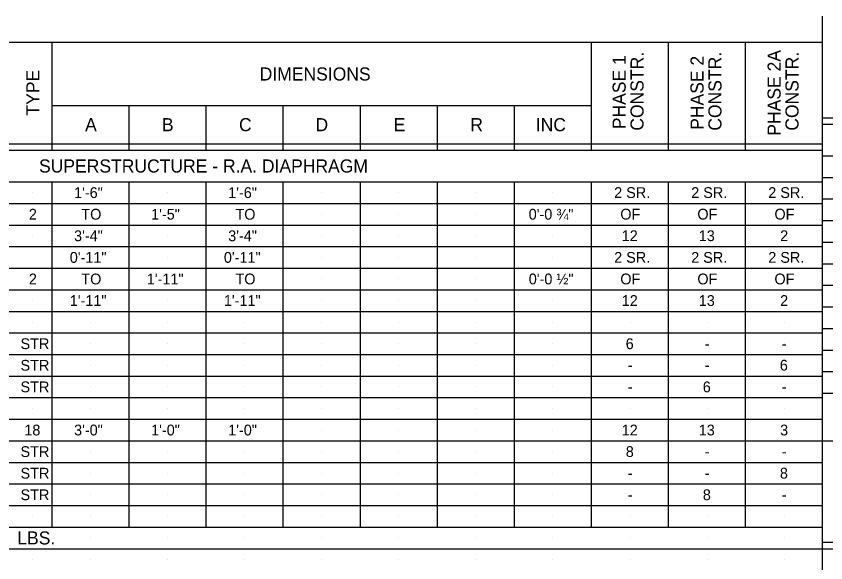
# Model space of a CAD drawing. Extents: x 0 to 34, y 0 to 22.
# Drawn here: x 6.29 to 16.8, y 7.18 to 14.27 of the extents above; entities that cross this region are included whole.
import ezdxf

# ---------------------------------------------------------------- set-up
doc = ezdxf.new("R2010")
doc.units = 0
doc.layers.add('BR_P_Gen_Text', color=7, linetype='Continuous')

msp = doc.modelspace()

# ---------------------------------------------------------------- linework, layer by layer
at = {"layer": 'BR_P_Gen_Text'}
for p, q in [((16.76, 7.701), (16.76, 14.272)), ((16.76, 3.872), (16.76, 14.272)), ((1.593, 13.935), (16.76, 13.935)), ((6.76, 12.535), (6.76, 13.935)), ((13.76, 12.535), (13.76, 13.935)), ((14.76, 12.535), (14.76, 13.935)), ((15.76, 12.535), (15.76, 13.935)), ((6.76, 13.112), (13.76, 13.112)), ((7.76, 12.535), (7.76, 13.112)), ((8.76, 12.535), (8.76, 13.112)), ((9.76, 12.535), (9.76, 13.112)), ((10.76, 12.535), (10.76, 13.112)), ((11.76, 12.535), (11.76, 13.112)), ((12.76, 12.535), (12.76, 13.112)), ((16.76, 12.955), (31.927, 12.955)), ((16.76, 12.872), (31.927, 12.872)), ((1.593, 12.617), (16.76, 12.618)), ((1.593, 12.535), (16.76, 12.535)), ((16.76, 12.461), (31.927, 12.461)), ((7.677, 12.329), (7.677, 12.329)), ((1.593, 12.123), (16.76, 12.124)), ((6.76, 7.643), (6.76, 12.123)), ((7.76, 7.643), (7.76, 12.123)), ((8.76, 7.643), (8.76, 12.123)), ((9.76, 7.643), (9.76, 12.123)), ((10.76, 7.643), (10.76, 12.123)), ((11.76, 7.643), (11.76, 12.123)), ((12.76, 7.643), (12.76, 12.123)), ((13.76, 7.643), (13.76, 12.124)), ((14.76, 7.643), (14.76, 12.124)), ((15.76, 7.643), (15.76, 12.124)), ((16.76, 12.181), (31.927, 12.181)), ((6.51, 11.983), (6.51, 11.983)), ((7.26, 11.983), (7.26, 11.983)), ((8.26, 11.983), (8.26, 11.983)), ((9.26, 11.983), (9.26, 11.983)), ((10.26, 11.983), (10.26, 11.983)), ((11.26, 11.983), (11.26, 11.983)), ((12.26, 11.983), (12.26, 11.983)), ((13.26, 11.983), (13.26, 11.983)), ((14.26, 11.983), (14.26, 11.983)), ((15.26, 11.984), (15.26, 11.984)), ((16.26, 11.984), (16.26, 11.984)), ((16.76, 11.901), (31.927, 11.901)), ((1.593, 11.843), (16.76, 11.843)), ((6.51, 11.703), (6.51, 11.703)), ((7.26, 11.703), (7.26, 11.703)), ((8.26, 11.703), (8.26, 11.703)), ((9.26, 11.703), (9.26, 11.703)), ((10.26, 11.703), (10.26, 11.703)), ((11.26, 11.703), (11.26, 11.703)), ((12.26, 11.703), (12.26, 11.703)), ((13.26, 11.703), (13.26, 11.703)), ((14.26, 11.703), (14.26, 11.703)), ((15.26, 11.703), (15.26, 11.703)), ((16.26, 11.703), (16.26, 11.703)), ((1.593, 11.563), (16.76, 11.563)), ((16.76, 11.621), (31.927, 11.621)), ((6.51, 11.423), (6.51, 11.423)), ((7.26, 11.423), (7.26, 11.423)), ((8.26, 11.423), (8.26, 11.423)), ((9.26, 11.423), (9.26, 11.423)), ((10.26, 11.423), (10.26, 11.423)), ((11.26, 11.423), (11.26, 11.423)), ((12.26, 11.423), (12.26, 11.423)), ((13.26, 11.423), (13.26, 11.423)), ((14.26, 11.423), (14.26, 11.423)), ((15.26, 11.423), (15.26, 11.423)), ((16.26, 11.423), (16.26, 11.423)), ((1.593, 11.283), (16.76, 11.283)), ((16.76, 11.341), (31.927, 11.341)), ((7.26, 11.143), (7.26, 11.143)), ((8.26, 11.143), (8.26, 11.143)), ((9.26, 11.143), (9.26, 11.143)), ((10.26, 11.143), (10.26, 11.143)), ((11.26, 11.143), (11.26, 11.143)), ((12.26, 11.143), (12.26, 11.143)), ((13.26, 11.143), (13.26, 11.143)), ((14.26, 11.143), (14.26, 11.143)), ((15.26, 11.143), (15.26, 11.143)), ((16.26, 11.143), (16.26, 11.143)), ((16.76, 11.061), (31.927, 11.061)), ((1.593, 11.003), (16.76, 11.003)), ((6.51, 10.863), (6.51, 10.863)), ((7.26, 10.863), (7.26, 10.863)), ((8.26, 10.863), (8.26, 10.863)), ((9.26, 10.863), (9.26, 10.863)), ((10.26, 10.863), (10.26, 10.863)), ((11.26, 10.863), (11.26, 10.863)), ((12.26, 10.863), (12.26, 10.863)), ((13.26, 10.863), (13.26, 10.863)), ((14.26, 10.863), (14.26, 10.863)), ((15.26, 10.863), (15.26, 10.863)), ((16.26, 10.863), (16.26, 10.863)), ((1.593, 10.723), (16.76, 10.723)), ((16.76, 10.781), (31.927, 10.781)), ((6.51, 10.583), (6.51, 10.583)), ((7.26, 10.583), (7.26, 10.583)), ((8.26, 10.583), (8.26, 10.583)), ((9.26, 10.583), (9.26, 10.583)), ((10.26, 10.583), (10.26, 10.583)), ((11.26, 10.583), (11.26, 10.583)), ((12.26, 10.583), (12.26, 10.583)), ((13.26, 10.583), (13.26, 10.583)), ((14.26, 10.583), (14.26, 10.583)), ((15.26, 10.583), (15.26, 10.583)), ((16.26, 10.583), (16.26, 10.583)), ((1.593, 10.443), (16.76, 10.443)), ((16.76, 10.501), (31.927, 10.501)), ((6.51, 10.303), (6.51, 10.303)), ((7.26, 10.303), (7.26, 10.303)), ((8.26, 10.303), (8.26, 10.303)), ((9.26, 10.303), (9.26, 10.303)), ((10.26, 10.303), (10.26, 10.303)), ((11.26, 10.303), (11.26, 10.303)), ((12.26, 10.303), (12.26, 10.303)), ((13.26, 10.303), (13.26, 10.303)), ((14.26, 10.303), (14.26, 10.303)), ((15.26, 10.303), (15.26, 10.303)), ((16.26, 10.303), (16.26, 10.303)), ((16.76, 10.221), (31.927, 10.221)), ((1.593, 10.163), (16.76, 10.163)), ((6.51, 10.023), (6.51, 10.023)), ((6.51, 10.023), (6.51, 10.023)), ((7.26, 10.023), (7.26, 10.023)), ((7.26, 10.023), (7.26, 10.023)), ((8.26, 10.023), (8.26, 10.023)), ((8.26, 10.023), (8.26, 10.023)), ((9.26, 10.023), (9.26, 10.023)), ((9.26, 10.023), (9.26, 10.023)), ((10.26, 10.023), (10.26, 10.023)), ((10.26, 10.023), (10.26, 10.023)), ((11.26, 10.023), (11.26, 10.023)), ((11.26, 10.023), (11.26, 10.023)), ((12.26, 10.023), (12.26, 10.023)), ((12.26, 10.023), (12.26, 10.023)), ((13.26, 10.023), (13.26, 10.023)), ((13.26, 10.023), (13.26, 10.023)), ((14.26, 10.023), (14.26, 10.023)), ((15.26, 10.023), (15.26, 10.023)), ((16.26, 10.023), (16.26, 10.023)), ((1.593, 9.883), (16.76, 9.883)), ((16.76, 9.941), (31.927, 9.941)), ((6.51, 9.743), (6.51, 9.743)), ((6.51, 9.743), (6.51, 9.743)), ((7.26, 9.743), (7.26, 9.743)), ((7.26, 9.743), (7.26, 9.743)), ((8.26, 9.743), (8.26, 9.743)), ((8.26, 9.743), (8.26, 9.743)), ((9.26, 9.743), (9.26, 9.743)), ((9.26, 9.743), (9.26, 9.743)), ((10.26, 9.743), (10.26, 9.743)), ((10.26, 9.743), (10.26, 9.743)), ((11.26, 9.743), (11.26, 9.743)), ((11.26, 9.743), (11.26, 9.743)), ((12.26, 9.743), (12.26, 9.743)), ((12.26, 9.743), (12.26, 9.743)), ((13.26, 9.743), (13.26, 9.743)), ((13.26, 9.743), (13.26, 9.743)), ((14.26, 9.743), (14.26, 9.743)), ((14.26, 9.743), (14.26, 9.743)), ((15.26, 9.744), (15.26, 9.744)), ((15.26, 9.743), (15.26, 9.743)), ((16.26, 9.744), (16.26, 9.744)), ((16.26, 9.743), (16.26, 9.743)), ((1.593, 9.603), (16.76, 9.604)), ((16.76, 9.661), (31.927, 9.661)), ((6.51, 9.463), (6.51, 9.463)), ((7.26, 9.463), (7.26, 9.463)), ((8.26, 9.463), (8.26, 9.463)), ((9.26, 9.463), (9.26, 9.463)), ((10.26, 9.463), (10.26, 9.463)), ((11.26, 9.463), (11.26, 9.463)), ((12.26, 9.463), (12.26, 9.463)), ((13.26, 9.463), (13.26, 9.463)), ((14.26, 9.463), (14.26, 9.463)), ((15.26, 9.463), (15.26, 9.463)), ((16.26, 9.463), (16.26, 9.463)), ((16.76, 9.381), (31.927, 9.381)), ((1.593, 9.323), (16.76, 9.323)), ((6.51, 9.183), (6.51, 9.183)), ((7.26, 9.183), (7.26, 9.183)), ((8.26, 9.183), (8.26, 9.183)), ((9.26, 9.183), (9.26, 9.183)), ((10.26, 9.183), (10.26, 9.183)), ((11.26, 9.183), (11.26, 9.183)), ((12.26, 9.183), (12.26, 9.183)), ((13.26, 9.183), (13.26, 9.183)), ((14.26, 9.183), (14.26, 9.183)), ((15.26, 9.183), (15.26, 9.183)), ((16.26, 9.183), (16.26, 9.183)), ((1.593, 9.043), (16.76, 9.043)), ((6.51, 8.903), (6.51, 8.903)), ((7.26, 8.903), (7.26, 8.903)), ((8.26, 8.903), (8.26, 8.903)), ((9.26, 8.903), (9.26, 8.903)), ((10.26, 8.903), (10.26, 8.903)), ((11.26, 8.903), (11.26, 8.903)), ((12.26, 8.903), (12.26, 8.903)), ((13.26, 8.903), (13.26, 8.903)), ((14.26, 8.903), (14.26, 8.903)), ((15.26, 8.903), (15.26, 8.903)), ((16.26, 8.903), (16.26, 8.903)), ((1.593, 8.763), (16.76, 8.763)), ((16.76, 8.763), (31.927, 8.764)), ((6.51, 8.623), (6.51, 8.623)), ((7.26, 8.623), (7.26, 8.623)), ((8.26, 8.623), (8.26, 8.623)), ((9.26, 8.623), (9.26, 8.623)), ((10.26, 8.623), (10.26, 8.623)), ((11.26, 8.623), (11.26, 8.623)), ((12.26, 8.623), (12.26, 8.623)), ((13.26, 8.623), (13.26, 8.623)), ((14.26, 8.623), (14.26, 8.623)), ((15.26, 8.623), (15.26, 8.623)), ((16.26, 8.623), (16.26, 8.623)), ((1.593, 8.483), (16.76, 8.483)), ((6.51, 8.343), (6.51, 8.343)), ((7.26, 8.343), (7.26, 8.343)), ((8.26, 8.343), (8.26, 8.343)), ((9.26, 8.343), (9.26, 8.343)), ((10.26, 8.343), (10.26, 8.343)), ((11.26, 8.343), (11.26, 8.343)), ((12.26, 8.343), (12.26, 8.343)), ((13.26, 8.343), (13.26, 8.343)), ((14.26, 8.343), (14.26, 8.343)), ((15.26, 8.343), (15.26, 8.343)), ((16.26, 8.343), (16.26, 8.343)), ((1.593, 8.203), (16.76, 8.203)), ((6.51, 8.063), (6.51, 8.063)), ((7.26, 8.063), (7.26, 8.063)), ((8.26, 8.063), (8.26, 8.063)), ((9.26, 8.063), (9.26, 8.063)), ((10.26, 8.063), (10.26, 8.063)), ((11.26, 8.063), (11.26, 8.063)), ((12.26, 8.063), (12.26, 8.063)), ((13.26, 8.063), (13.26, 8.063)), ((14.26, 8.063), (14.26, 8.063)), ((15.26, 8.063), (15.26, 8.063)), ((16.26, 8.063), (16.26, 8.063)), ((1.593, 7.923), (16.76, 7.923)), ((6.51, 7.783), (6.51, 7.783)), ((7.26, 7.783), (7.26, 7.783)), ((8.26, 7.783), (8.26, 7.783)), ((9.26, 7.783), (9.26, 7.783)), ((10.26, 7.783), (10.26, 7.783)), ((11.26, 7.783), (11.26, 7.783)), ((12.26, 7.783), (12.26, 7.783)), ((13.26, 7.783), (13.26, 7.783)), ((14.26, 7.783), (14.26, 7.783)), ((15.26, 7.783), (15.26, 7.783)), ((16.26, 7.783), (16.26, 7.783)), ((1.593, 7.643), (16.76, 7.643)), ((6.51, 7.503), (6.51, 7.503)), ((7.26, 7.503), (7.26, 7.503)), ((8.26, 7.503), (8.26, 7.503)), ((9.26, 7.503), (9.26, 7.503)), ((10.26, 7.503), (10.26, 7.503)), ((11.26, 7.503), (11.26, 7.503)), ((12.26, 7.503), (12.26, 7.503)), ((13.26, 7.503), (13.26, 7.503)), ((14.26, 7.503), (14.26, 7.503)), ((15.26, 7.503), (15.26, 7.503)), ((16.26, 7.503), (16.26, 7.503)), ((1.593, 7.363), (16.76, 7.363)), ((16.76, 7.446), (31.927, 7.446)), ((16.76, 7.363), (31.927, 7.363)), ((6.51, 7.223), (6.51, 7.223)), ((6.51, 7.223), (6.51, 7.223)), ((7.26, 7.223), (7.26, 7.223)), ((7.26, 7.223), (7.26, 7.223)), ((8.26, 7.223), (8.26, 7.223)), ((8.26, 7.223), (8.26, 7.223)), ((9.26, 7.223), (9.26, 7.223)), ((9.26, 7.223), (9.26, 7.223)), ((10.26, 7.223), (10.26, 7.223)), ((10.26, 7.223), (10.26, 7.223)), ((11.26, 7.223), (11.26, 7.223)), ((11.26, 7.223), (11.26, 7.223)), ((12.26, 7.223), (12.26, 7.223)), ((12.26, 7.223), (12.26, 7.223)), ((13.26, 7.223), (13.26, 7.223)), ((13.26, 7.223), (13.26, 7.223)), ((14.26, 7.223), (14.26, 7.223)), ((15.26, 7.223), (15.26, 7.223)), ((16.26, 7.223), (16.26, 7.223))]:
    msp.add_line(p, q, dxfattribs=at)

# ---------------------------------------------------------------- texts
for s, p in [('CONSTR.', (14.436, 12.787)), ('CONSTR.', (15.447, 12.787)), ('PHASE 2A', (16.215, 12.722)), ('CONSTR.', (16.447, 12.787)), ('PHASE 1', (14.204, 12.806)), ('PHASE 2', (15.215, 12.798)), ('TYPE', (6.595, 12.983))]:
    msp.add_text(s, height=0.17, rotation=90, dxfattribs=at).set_placement(p)
for s, height, p in [('DIMENSIONS', 0.17, (9.454, 13.438)), ('A', 0.17, (7.188, 12.78)), ('B', 0.17, (8.185, 12.78)), ('C', 0.17, (9.185, 12.78)), ('D', 0.17, (10.178, 12.78)), ('E', 0.17, (11.192, 12.78)), ('R', 0.17, (12.187, 12.78)), ('INC', 0.17, (13.037, 12.78)), ('SUPERSTRUCTURE - R.A. DIAPHRAGM', 0.17, (6.59, 12.244)), ('1\'-6"', 0.14, (7.045, 11.913)), ('1\'-6"', 0.14, (9.045, 11.913)), ('2 SR.', 0.14, (14.054, 11.914)), ('2 SR.', 0.14, (15.054, 11.914)), ('2 SR.', 0.14, (16.054, 11.914)), ('2', 0.14, (6.458, 11.633)), ('TO', 0.14, (7.139, 11.633)), ('1\'-5"', 0.14, (8.045, 11.633)), ('TO', 0.14, (9.139, 11.633)), ('0\'-0 ¾"', 0.14, (12.945, 11.633)), ('OF', 0.14, (14.134, 11.634)), ('OF', 0.14, (15.134, 11.634)), ('OF', 0.14, (16.134, 11.634)), ('3\'-4"', 0.14, (7.045, 11.353)), ('3\'-4"', 0.14, (9.045, 11.353)), ('12', 0.14, (14.152, 11.354)), ('13', 0.14, (15.152, 11.354)), ('2', 0.14, (16.208, 11.354)), ('0\'-11"', 0.14, (6.989, 11.073)), ('0\'-11"', 0.14, (8.989, 11.073)), ('2 SR.', 0.14, (14.054, 11.073)), ('2 SR.', 0.14, (15.054, 11.073)), ('2 SR.', 0.14, (16.054, 11.073)), ('2', 0.14, (6.458, 10.793)), ('TO', 0.14, (7.139, 10.793)), ('1\'-11"', 0.14, (7.989, 10.793)), ('TO', 0.14, (9.139, 10.793)), ('0\'-0 ½"', 0.14, (12.946, 10.793)), ('OF', 0.14, (14.134, 10.793)), ('OF', 0.14, (15.134, 10.793)), ('OF', 0.14, (16.134, 10.793)), ('1\'-11"', 0.14, (6.989, 10.513)), ('1\'-11"', 0.14, (8.989, 10.513)), ('12', 0.14, (14.152, 10.513)), ('13', 0.14, (15.152, 10.513)), ('2', 0.14, (16.208, 10.513)), ('STR', 0.14, (6.35, 9.953)), ('6', 0.14, (14.204, 9.953)), ('-', 0.14, (15.23, 9.953)), ('-', 0.14, (16.23, 9.953)), ('STR', 0.14, (6.35, 9.673)), ('6', 0.14, (16.204, 9.674)), ('-', 0.14, (14.23, 9.674)), ('-', 0.14, (15.23, 9.674)), ('STR', 0.14, (6.35, 9.393)), ('6', 0.14, (15.204, 9.393)), ('-', 0.14, (14.23, 9.393)), ('-', 0.14, (16.23, 9.393)), ('18', 0.14, (6.399, 8.833)), ('3\'-0"', 0.14, (7.045, 8.833)), ('1\'-0"', 0.14, (8.045, 8.833)), ('1\'-0"', 0.14, (9.045, 8.833)), ('12', 0.14, (14.152, 8.833)), ('13', 0.14, (15.152, 8.833)), ('3', 0.14, (16.208, 8.833)), ('STR', 0.14, (6.35, 8.553)), ('8', 0.14, (14.205, 8.553)), ('-', 0.14, (15.23, 8.553)), ('-', 0.14, (16.23, 8.553)), ('STR', 0.14, (6.35, 8.273)), ('8', 0.14, (16.205, 8.273)), ('-', 0.14, (14.23, 8.273)), ('-', 0.14, (15.23, 8.273)), ('STR', 0.14, (6.35, 7.993)), ('8', 0.14, (15.205, 7.993)), ('-', 0.14, (14.23, 7.993)), ('-', 0.14, (16.23, 7.993)), ('LBS.', 0.17, (6.308, 7.418))]:
    msp.add_text(s, height=height, dxfattribs=at).set_placement(p)

doc.saveas('drawing.dxf')
